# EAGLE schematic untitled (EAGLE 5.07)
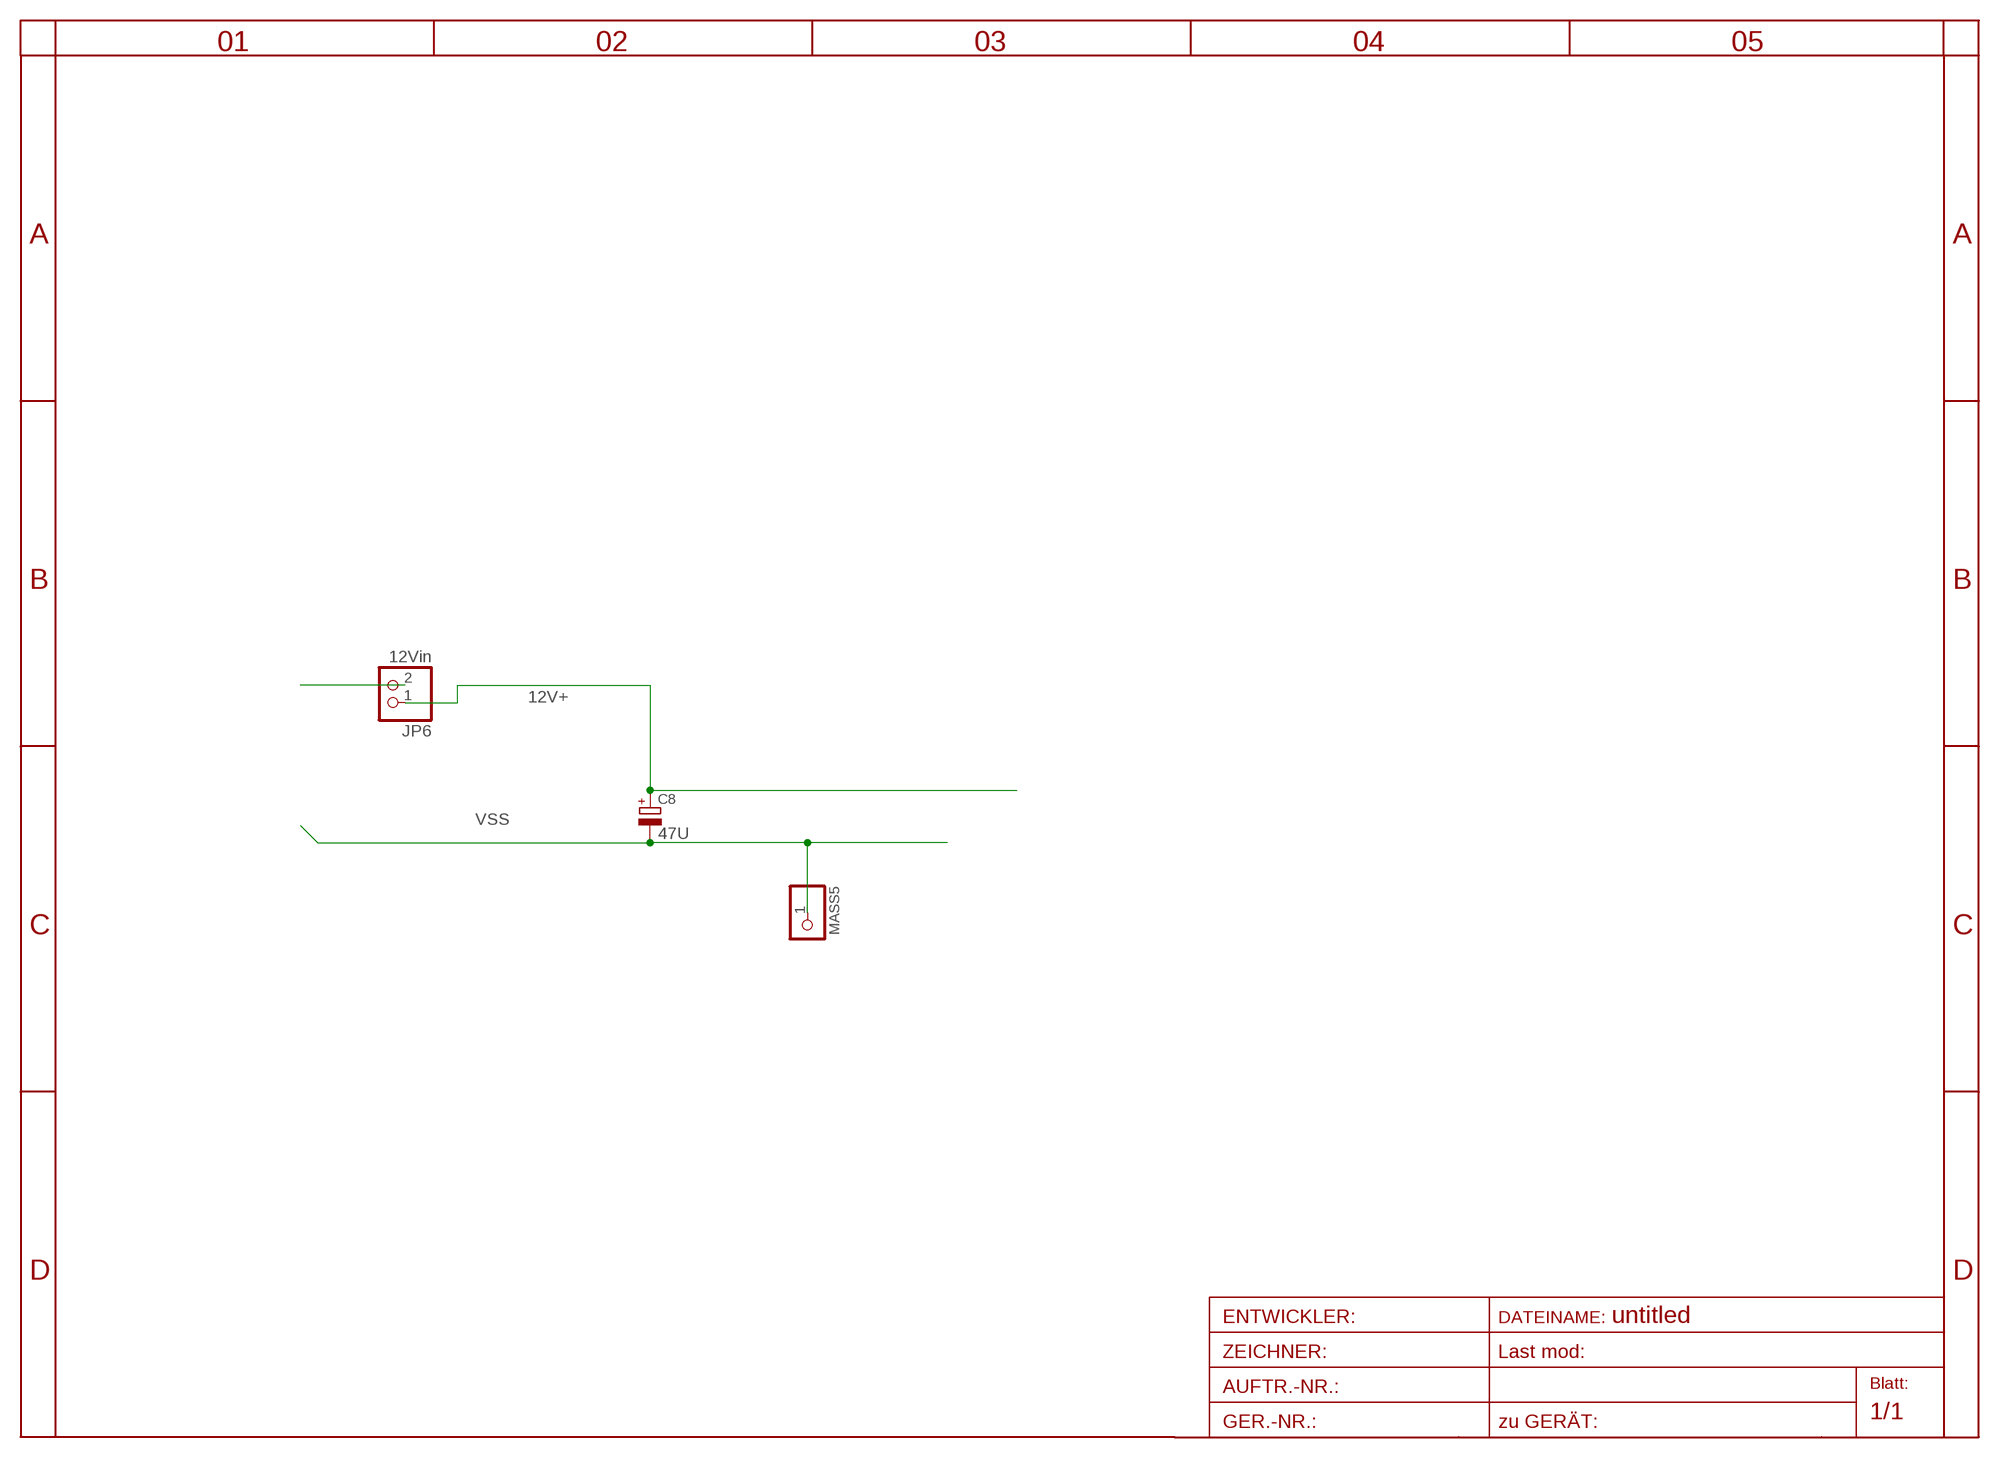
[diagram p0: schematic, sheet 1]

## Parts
C8  47U  CPOL-EUE5-5  [E5-5]
JP6  12Vin  PINHD-1X2STR  [1X02]
MASS5  PINHD-1X11MM6  [1X1MM8]

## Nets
12V+: C8.+ JP6.1
VSS: C8.- JP6.2 MASS5.1

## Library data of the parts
C8 = rcl-2:CPOL-EU: POLARIZED CAPACITOR, European symbol
JP6 = pinhead:PINHD-1X2: PIN HEADER
MASS5 = pinhead:PINHD-1X1: PIN HEADER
